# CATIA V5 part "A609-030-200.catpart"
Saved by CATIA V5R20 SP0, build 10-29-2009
Part number: A609-030-200
Source: Unknown
Property "ARTICLENO": "A609-030-200"
Property "B": "30.000"
Property "BOMINFO": "A609-030-200"
Property "CODE": "A609-030-200"
Property "D": "20.000"
Property "D1": "13.500"
Property "FORM": "B"
Property "L": "200.000"
Property "L1": "25.000"
Property "L2": "75.000"
Property "LINA": "A609-030-200"
Property "NB": "A609-030-200"
Property "NBSYN": "$CODE."
Property "NN": "A609"
Property "NT": "VDI 3357 E-Type Wear Plates, self-lubricating"
Property "S": "30.000"
Property "SUPPLIER": "CF"
Property "T": "13.000"
Property "W": "60.000"
Bounding box of the stored display mesh (mm): x 0 to 200, y 0 to 30, z 0 to 60
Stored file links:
  C:\Users\Utente\Desktop\3D files A609\A609-030-200.catpart
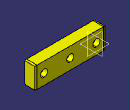
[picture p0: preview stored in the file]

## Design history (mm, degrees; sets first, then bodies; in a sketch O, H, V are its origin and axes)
Body1 "Geometry.1" (main body)
  Solid1 "A609-030-200catpart": solid without history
